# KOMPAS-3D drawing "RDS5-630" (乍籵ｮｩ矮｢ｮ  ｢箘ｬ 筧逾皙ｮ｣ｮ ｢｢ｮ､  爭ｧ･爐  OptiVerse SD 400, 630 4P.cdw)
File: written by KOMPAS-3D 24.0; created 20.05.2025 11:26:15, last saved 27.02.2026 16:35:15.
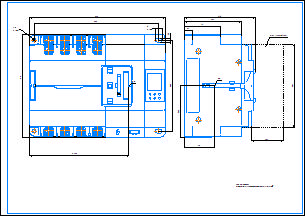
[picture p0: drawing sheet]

Document properties: Утвердил: Строгонов; Автор: ОґЦё¶Ё ОґЦё¶Ё ОґЦё¶Ё ОґЦё¶Ё ОґЦё¶Ё; Проверил: Дорошев; Форматы листов документа: A1; Полное имя файла: ..\..\OptiVerse SD 630 4P\3D\RDS5-630A.a3d; Масса: 8.9; Т. контр.: Пашков А.Е.; Наименование: Устройство автоматического ввода резерва OptiVerse SD 400 4P / Габаритный чертеж; Н. контр.: Гаврикова; Количество листов документа: 1; Разработал: Сулейманова; Организация: ОґЦё¶Ё

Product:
- Component [assembly]: RDS5-630.STEP  | qty 1  | Масса: 85.332108; source file: ..\..\OptiVerse SD 630 4P\3D\RDS5-630.STEP.a3d
- Body: Тело 1
    Масса: 0.000012
- Part/product: RDS5-630
    Масса: 85.332121
    Форматы листов документа: A1

Referenced files in D:\Проекты\OptiVerse SD\OptiVerse SD\OptiVerse SD 630 4P\КД\: ГЖИК.648476.002СБ Устройство автоматического  ввода резерва OptiVerse SD 630 4P.cdw
Referenced files in D:\Проекты\OptiVerse SD\OptiVerse SD\OptiVerse SD 630 4P\3D\: RDS5-630A.a3d, 630______________________________________________________________________________________.STEP.m3d, __________________t___1_______t____1__________t___1_____________t____1________________t.STEP.a3d, 630________.STEP.m3d, 630o____________________________________o___________o_______.STEP.m3d, 630___11__________________________.STEP.m3d, 125_____________a1______a1________a1__1___a1__1_____a1__1.STEP.m3d, 125__________111.STEP.m3d, _________t_______t__________t________t__________t.STEP.a3d, 630_DD_Dy__a___y___a_____y_____a_________a____________a___________.STEP.m3d, 630__2_________________________.STEP.m3d, M4X8_1.STEP.m3d, ___11111111.STEP.a3d, 630-________-____a-_____a-____a-_____a-__.STEP.m3d, ________-_______t_________t____________t____________t_______________t.STEP.a3d, 630-3_______-____a-_____a-____a-_____a-__.STEP.m3d, 3_______-_______t_________t____________t____________t_______________t.STEP.a3d, ______________.STEP.m3d, 630-_o____-____a-_____a-__-__-__.STEP.m3d, ______2_2_2_2_2.STEP.m3d, M10-30_GB_FASTENER_SCREWS_HSHCS M10X16-C.STEP.m3d, 1P.STEP.a3d, ________-_______t_________t____________t____________t_______________t.STEP-1.a3d, 3_______-_______t_________t____________t____________t_______________t.STEP-1.a3d, 1P.STEP-1.a3d, ________-_______t_________t____________t____________t_______________t.STEP-2.a3d, 3_______-_______t_________t____________t____________t_______________t.STEP-2.a3d, 1P.STEP-2.a3d, ________-_______t_________t____________t____________t_______________t.STEP-3.a3d, 3_______-_______t_________t____________t____________t_______________t.STEP-3.a3d, 1P.STEP-3.a3d, _________t_______t__________t________t__________t.STEP-1.a3d, 2EDG-2P2_____________________1____1____1.STEP.m3d, 2EDG-______________111.STEP.m3d, 2EDG-2P_____2_____2________2____________1__________1____________1.STEP.a3d, 2EDG-2P___________________o____________o_____________1______________1_________________1.STEP.a3d, 2EDG-2P_____2_____2________2____________1__________1____________1.STEP-1.a3d, 2EDG-2P___________________o____________o_____________1______________1_________________1.STEP-1.a3d, 2EDG-3P2_____________________1____1____1.STEP.m3d, 2EDG-3P_____2_____2________2____________1__________1____________1.STEP.a3d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
Referenced files: 630______________________________________________________________________________________.STEP, 630______________________________________________________________________________________.STEP 630______________________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, 630________.STEP, 630________.STEP 630________.STEP, 630o____________________________________o___________o_______.STEP, 630o____________________________________o___________o_______.STEP 630o____________________________________o___________o_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, 630___11__________________________.STEP, 630___11__________________________.STEP 630___11__________________________.STEP, 125_____________a1______a1________a1__1___a1__1_____a1__1.STEP, 125_____________a1______a1________a1__1___a1__1_____a1__1.STEP 125_____________a1______a1________a1__1___a1__1_____a1__1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, 125__________111.STEP, 125__________111.STEP 125__________111.STEP, 630_DD_Dy__a___y___a_____y_____a_________a____________a___________.STEP, 630_DD_Dy__a___y___a_____y_____a_________a____________a___________.STEP 630_DD_Dy__a___y___a_____y_____a_________a______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, 630__2_________________________.STEP, 630__2_________________________.STEP 630__2_________________________.STEP, M4X8_1.STEP, M4X8_1.STEP M4X8_1.STEP, 630-________-____a-_____a-____a-_____a-__.STEP, 630-________-____a-_____a-____a-_____a-__.STEP 630-________-____a-_____a-____a-_____a-__.STEP, 630-3_______-____a-_____a-____a-_____a-__.STEP, 630-3_______-____a-_____a-____a-_____a-__.STEP 630-3_______-____a-_____a-____a-_____a-__.STEP, 3_______-_______t_________t____________t____________t_______________t.STEP, 3_______-_______t_________t____________t____________t_______________t.STEP 3_______-_______t_________t____________t_____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, 630-_o____-____a-_____a-__-__-__.STEP, 630-_o____-____a-_____a-__-__-__.STEP 630-_o____-____a-_____a-__-__-__.STEP, M10-30_GB_FASTENER_SCREWS_HSHCS M10X16-C.STEP, M10-30_GB_FASTENER_SCREWS_HSHCS M10X16-C.STEP M10-30_GB_FASTENER_SCREWS_HSHCS M10X16-C.STEP, 1P.STEP, 1P.STEP 1P.STEP, 2EDG-2P2_____________________1____1____1.STEP, 2EDG-2P2_____________________1____1____1.STEP 2EDG-2P2_____________________1____1____1.STEP, 2EDG-______________111.STEP, 2EDG-______________111.STEP 2EDG-______________111.STEP, 2EDG-2P_____2_____2________2____________1__________1____________1.STEP, 2EDG-2P_____2_____2________2____________1__________1____________1.STEP 2EDG-2P_____2_____2________2____________1________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, 2EDG-2P___________________o____________o_____________1______________1_________________1.STEP, 2EDG-2P___________________o____________o_____________1______________1_________________1.STEP 2EDG-2P___________________o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, 2EDG-3P2_____________________1____1____1.STEP, 2EDG-3P2_____________________1____1____1.STEP 2EDG-3P2_____________________1____1____1.STEP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
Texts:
  Устройство автоматического
  ввода резерва OptiVerse SD 400 4P
  Габаритный чертеж
  ГЖИК.648466.002ГЧ
  ГЖИК.648466.002
  Сулейманова
  Дорошев
  АО "КЭАЗ"
  Гаврикова
  Строгонов
  Пашков А.Е.
  Без основной надписи.
  3_______-_______t_________t____________t____________t_______________t.STEP-1
  3_______-_______t_________t____________t____________t_______________t.STEP-1 3_______-_______t_________t____________t____________t_______________t.STEP-1
  3_______-_______t_________t____________t____________t_______________t.STEP-2
  3_______-_______t_________t____________t____________t_______________t.STEP-2 3_______-_______t_________t____________t____________t_______________t.STEP-2
  3_______-_______t_________t____________t____________t_______________t.STEP-3
  3_______-_______t_________t____________t____________t_______________t.STEP-3 3_______-_______t_________t____________t____________t_______________t.STEP-3
  2EDG-2P_____2_____2________2____________1__________1____________1.STEP-1
  2EDG-2P_____2_____2________2____________1__________1____________1.STEP-1 2EDG-2P_____2_____2________2____________1__________1____________1.STEP-1
  2EDG-2P___________________o____________o_____________1______________1_________________1.STEP-1
  2EDG-2P___________________o____________o_____________1______________1_________________1.STEP-1 2EDG-2P___________________o____________o_____________1______________1_________________1.STEP-1
  2EDG-2P_____2_____2________2____________1__________1____________1.STEP-2
  2EDG-2P_____2_____2________2____________1__________1____________1.STEP-2 2EDG-2P_____2_____2________2____________1__________1____________1.STEP-2
  2EDG-2P___________________o____________o_____________1______________1_________________1.STEP-2
  2EDG-2P___________________o____________o_____________1______________1_________________1.STEP-2 2EDG-2P___________________o____________o_____________1______________1_________________1.STEP-2
  RDS5-630
  RDS5-630 RDS5-630
Dimensions and other numbers on the sheet: 1:1; 0; 1; 2; 8,9; 1P.STEP-1; 1P.STEP-1 1P.STEP-1; 1P.STEP-2; 1P.STEP-2 1P.STEP-2; 1P.STEP-3; 1P.STEP-3 1P.STEP-3

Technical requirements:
  Ц.М. - центр масс.
  Отклонение координат от центра масс не более 10 %.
